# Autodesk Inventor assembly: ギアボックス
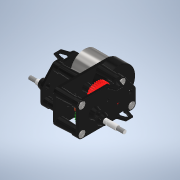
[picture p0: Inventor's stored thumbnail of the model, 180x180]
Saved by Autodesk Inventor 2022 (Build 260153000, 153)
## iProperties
Created: 2024-10
Part Number: ギアボックス
Document SubType Name: Assembly
Designer: shimizu
Author: shimizu
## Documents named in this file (12)
- C:\Users\shimizu\Documents\卒論2024\3DCAD\ギアボックス\組立図\ギアボックス.iam
- C:\Users\shimizu\Documents\卒論2024\3DCAD\ギアボックス\部品図\ギアケースA（中央）.ipt
- C:\Users\shimizu\Documents\卒論2024\3DCAD\ギアボックス\部品図\モーター.ipt
- C:\Users\shimizu\Documents\卒論2024\3DCAD\ギアボックス\部品図\ギアケースC（モーターヘッド側）.ipt
- C:\Users\shimizu\Documents\卒論2024\3DCAD\ギアボックス\部品図\ギアジョイント.ipt
- C:\Users\shimizu\Documents\卒論2024\3DCAD\ギアボックス\部品図\4mmシャフト.ipt
- C:\Users\shimizu\Documents\卒論2024\3DCAD\ギアボックス\部品図\ギアケースB（ギア側）.ipt
- C:\Users\shimizu\Documents\卒論2024\3DCAD\ギアボックス\部品図\38Tギア.ipt
- C:\Users\shimizu\Documents\卒論2024\3DCAD\ギアボックス\部品図\34T-12Tギア.iam
- C:\Users\shimizu\Documents\卒論2024\3DCAD\ギアボックス\部品図\10Tギア.ipt
- C:\Users\shimizu\Documents\卒論2024\3DCAD\ギアボックス\部品図\ねじ.ipt
- C:\Users\shimizu\Documents\卒論2024\3DCAD\ギアボックス\部品図\止めねじ.ipt
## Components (18 placed, 10 different names)
1. ギアケースA（中央）:1 — メイト:1, メイト:2, メイト:3, メイト:4, メイト:5, メイト:6, メイト:7, メイト:8, メイト:9, メイト:10, メイト:29, メイト:30, メイト:31, メイト:32, 角度:2
2. モーター:1 — メイト:1, メイト:2, 角度:1, メイト:33
3. ギアケースC（モーターヘッド側）:1 — メイト:3, メイト:4, メイト:5, 角度:1, メイト:42, メイト:43, メイト:44, メイト:45, メイト:46, メイト:47
4. ギアジョイント:1 — メイト:6, メイト:7, リジッド:1, メイト:26, メイト:27, メイト:48, メイト:49
5. 4mmシャフト:1 — リジッド:1, メイト:28
6. ギアケースB（ギア側）:1 — メイト:8, メイト:9, メイト:10, メイト:34, メイト:35, メイト:36, メイト:37, メイト:38, メイト:39, メイト:40, メイト:41
7. 平歯車1:1 — メイト:26, メイト:27, メイト:28, 回転:1
8. 34T-12Tギア:1 [sub-assembly] — メイト:31, メイト:32, 回転:1, 回転:2
9. 34T-12Tギア:2 [sub-assembly] — メイト:29, メイト:30, フラッシュ:2, 回転:2, 回転:3
10. 平歯車1:2 — フラッシュ:2, メイト:33, 回転:3, 角度:2
11. JIS B 1111 M3x8:1 — メイト:34, メイト:35
12. JIS B 1111 M3x8:2 — メイト:46, メイト:47
13. JIS B 1111 M3x8:3 — メイト:36, メイト:37
14. JIS B 1111 M3x8:4 — メイト:40, メイト:41
15. JIS B 1111 M3x8:5 — メイト:38, メイト:39
16. JIS B 1111 M3x8:6 — メイト:44, メイト:45
17. JIS B 1111 M3x8:7 — メイト:42, メイト:43
18. JIS B 1177 くぼみ先 - メートル M3 x 3:1 — メイト:48, メイト:49
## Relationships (41: Mate 34, RelateRotation 3, Angle 2, WeldJoint 1, Flush 1)
- メイト:1 [Mate]: ギアケースA（中央）:1 ↔ モーター:1
- メイト:2 [Mate]: ギアケースA（中央）:1 ↔ モーター:1
- メイト:3 [Mate]: ギアケースA（中央）:1 ↔ ギアケースC（モーターヘッド側）:1
- メイト:4 [Mate]: ギアケースA（中央）:1 ↔ ギアケースC（モーターヘッド側）:1
- メイト:5 [Mate]: ギアケースA（中央）:1 ↔ ギアケースC（モーターヘッド側）:1
- 角度:1 [Angle]: モーター:1 ↔ ギアケースC（モーターヘッド側）:1
- メイト:6 [Mate]: ギアケースA（中央）:1 ↔ ギアジョイント:1
- メイト:7 [Mate]: ギアケースA（中央）:1 ↔ ギアジョイント:1
- リジッド:1 [WeldJoint]: ギアジョイント:1 ↔ 4mmシャフト:1
- メイト:8 [Mate]: ギアケースA（中央）:1 ↔ ギアケースB（ギア側）:1
- メイト:9 [Mate]: ギアケースA（中央）:1 ↔ ギアケースB（ギア側）:1
- メイト:10 [Mate]: ギアケースA（中央）:1 ↔ ギアケースB（ギア側）:1
- メイト:26 [Mate]: ギアジョイント:1 ↔ 平歯車1:1
- メイト:27 [Mate]: ギアジョイント:1 ↔ 平歯車1:1
- メイト:28 [Mate]: 4mmシャフト:1 ↔ 平歯車1:1
- メイト:29 [Mate]: ギアケースA（中央）:1 ↔ 34T-12Tギア:2
- メイト:30 [Mate]: ギアケースA（中央）:1 ↔ 34T-12Tギア:2
- メイト:31 [Mate]: ギアケースA（中央）:1 ↔ 34T-12Tギア:1
- メイト:32 [Mate]: ギアケースA（中央）:1 ↔ 34T-12Tギア:1
- フラッシュ:2 [Flush]: 34T-12Tギア:2 ↔ 平歯車1:2
- メイト:33 [Mate]: モーター:1 ↔ 平歯車1:2
- 回転:1 [RelateRotation]: 平歯車1:1 ↔ 34T-12Tギア:1
- 回転:2 [RelateRotation]: 34T-12Tギア:1 ↔ 34T-12Tギア:2
- 回転:3 [RelateRotation]: 34T-12Tギア:2 ↔ 平歯車1:2
- 角度:2 [Angle]: ギアケースA（中央）:1 ↔ 平歯車1:2
- メイト:34 [Mate]: ギアケースB（ギア側）:1 ↔ JIS B 1111 M3x8:1
- メイト:35 [Mate]: ギアケースB（ギア側）:1 ↔ JIS B 1111 M3x8:1
- メイト:36 [Mate]: ギアケースB（ギア側）:1 ↔ JIS B 1111 M3x8:3
- メイト:37 [Mate]: ギアケースB（ギア側）:1 ↔ JIS B 1111 M3x8:3
- メイト:38 [Mate]: ギアケースB（ギア側）:1 ↔ JIS B 1111 M3x8:5
- メイト:39 [Mate]: ギアケースB（ギア側）:1 ↔ JIS B 1111 M3x8:5
- メイト:40 [Mate]: ギアケースB（ギア側）:1 ↔ JIS B 1111 M3x8:4
- メイト:41 [Mate]: ギアケースB（ギア側）:1 ↔ JIS B 1111 M3x8:4
- メイト:42 [Mate]: ギアケースC（モーターヘッド側）:1 ↔ JIS B 1111 M3x8:7
- メイト:43 [Mate]: ギアケースC（モーターヘッド側）:1 ↔ JIS B 1111 M3x8:7
- メイト:44 [Mate]: ギアケースC（モーターヘッド側）:1 ↔ JIS B 1111 M3x8:6
- メイト:45 [Mate]: ギアケースC（モーターヘッド側）:1 ↔ JIS B 1111 M3x8:6
- メイト:46 [Mate]: ギアケースC（モーターヘッド側）:1 ↔ JIS B 1111 M3x8:2
- メイト:47 [Mate]: ギアケースC（モーターヘッド側）:1 ↔ JIS B 1111 M3x8:2
- メイト:48 [Mate]: ギアジョイント:1 ↔ JIS B 1177 くぼみ先 - メートル M3 x 3:1
- メイト:49 [Mate]: ギアジョイント:1 ↔ JIS B 1177 くぼみ先 - メートル M3 x 3:1
